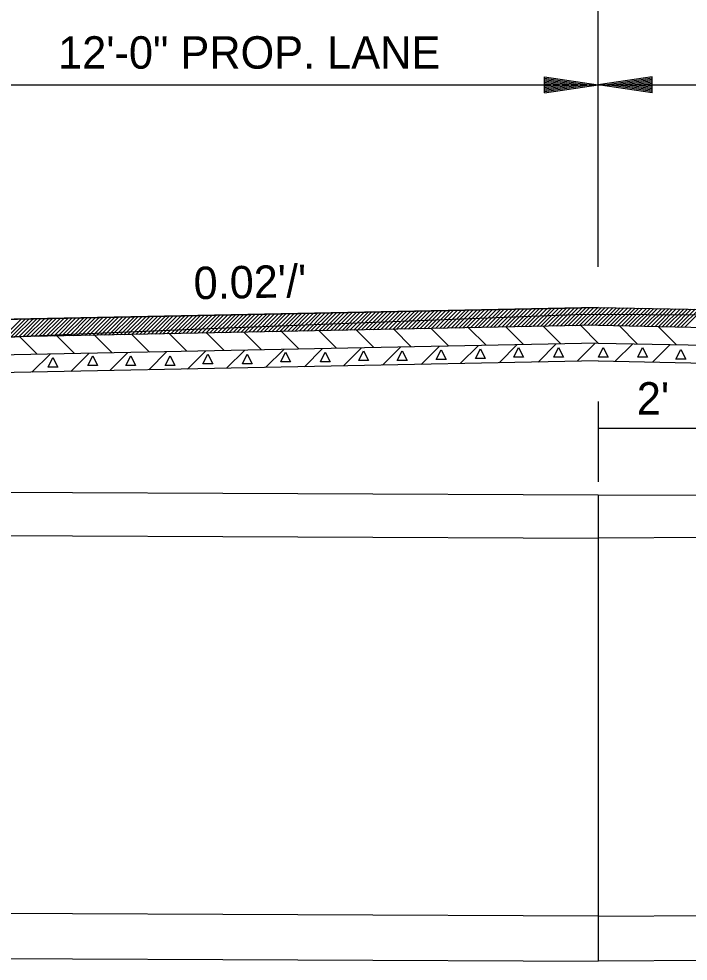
# Model space of a CAD drawing. Extents: x 1398460 to 1408037, y 380768 to 383968.
# Drawn here: x 1401391.5 to 1401515.5, y 383325.7 to 383500.2 of the extents above; entities that cross this region are included whole.
import ezdxf

# ---------------------------------------------------------------- set-up
doc = ezdxf.new("R2010")
doc.units = 0
for name, color, linetype in [('R_Dimension', 7, 'Continuous'), ('R_Draft', 7, 'Continuous'), ('R_Exist Surface', 7, 'Continuous'), ('R_Water', 7, 'Continuous')]:
    doc.layers.add(name, color=color, linetype=linetype)

msp = doc.modelspace()

# ---------------------------------------------------------------- linework, layer by layer
at = {"layer": 'R_Dimension'}
for p, q in [((1401498.88, 383454.27), (1401498.88, 383639.18)), ((1401488.88, 383489.49), (1401498.88, 383487.99)), ((1401488.88, 383486.49), (1401488.88, 383489.49)), ((1401488.88, 383489.24), (1401497.21, 383487.99)), ((1401488.88, 383488.98), (1401495.49, 383487.99)), ((1401488.88, 383488.73), (1401493.82, 383487.99)), ((1401488.88, 383488.48), (1401492.13, 383487.99)), ((1401488.88, 383488.22), (1401490.46, 383487.99)), ((1401508.88, 383489.49), (1401498.88, 383487.99)), ((1401508.88, 383489.24), (1401500.55, 383487.99)), ((1401508.88, 383488.98), (1401502.27, 383487.99)), ((1401508.88, 383488.73), (1401503.93, 383487.99)), ((1401508.88, 383488.48), (1401505.63, 383487.99)), ((1401508.88, 383488.22), (1401507.3, 383487.99)), ((1401508.88, 383486.49), (1401508.88, 383489.49)), ((1401378.88, 383487.99), (1401498.88, 383487.99)), ((1401488.88, 383486.49), (1401498.88, 383487.99)), ((1401488.88, 383487.5), (1401492.13, 383487.99)), ((1401488.88, 383486.99), (1401495.49, 383487.99)), ((1401488.88, 383486.74), (1401497.21, 383487.99)), ((1401488.88, 383487.24), (1401493.82, 383487.99)), ((1401488.88, 383487.75), (1401490.46, 383487.99)), ((1401508.88, 383486.49), (1401498.88, 383487.99)), ((1401498.88, 383487.99), (1401618.88, 383487.99)), ((1401508.88, 383486.74), (1401500.55, 383487.99)), ((1401508.88, 383486.99), (1401502.27, 383487.99)), ((1401508.88, 383487.24), (1401503.93, 383487.99)), ((1401508.88, 383487.5), (1401505.63, 383487.99)), ((1401508.88, 383487.75), (1401507.3, 383487.99)), ((1401498.88, 383429.35), (1401498.88, 383414.48)), ((1401518.88, 383424.35), (1401498.88, 383424.35))]:
    msp.add_line(p, q, dxfattribs=at)
at = {"layer": 'R_Draft'}
for p, q in [((1401498.88, 383446.78), (1401378.88, 383444.38)), ((1401467.26, 383442.84), (1401470.63, 383446.21)), ((1401467.98, 383442.86), (1401471.35, 383446.23)), ((1401468.71, 383442.87), (1401472.07, 383446.24)), ((1401469.43, 383442.89), (1401472.8, 383446.26)), ((1401470.15, 383442.9), (1401473.52, 383446.27)), ((1401470.87, 383442.92), (1401474.24, 383446.28)), ((1401471.59, 383442.93), (1401474.96, 383446.3)), ((1401472.31, 383442.95), (1401475.68, 383446.31)), ((1401473.04, 383442.96), (1401476.4, 383446.33)), ((1401473.76, 383442.97), (1401477.12, 383446.34)), ((1401474.48, 383442.99), (1401477.85, 383446.36)), ((1401475.2, 383443), (1401478.57, 383446.37)), ((1401475.92, 383443.02), (1401479.29, 383446.39)), ((1401476.64, 383443.03), (1401480.01, 383446.4)), ((1401477.36, 383443.05), (1401480.73, 383446.41)), ((1401478.09, 383443.06), (1401481.45, 383446.43)), ((1401478.81, 383443.08), (1401482.18, 383446.44)), ((1401479.53, 383443.09), (1401482.9, 383446.46)), ((1401480.25, 383443.1), (1401483.62, 383446.47)), ((1401480.97, 383443.12), (1401484.34, 383446.49)), ((1401481.69, 383443.13), (1401485.06, 383446.5)), ((1401482.42, 383443.15), (1401485.78, 383446.52)), ((1401483.14, 383443.16), (1401486.5, 383446.53)), ((1401483.86, 383443.18), (1401487.23, 383446.54)), ((1401484.58, 383443.19), (1401487.95, 383446.56)), ((1401485.3, 383443.21), (1401488.67, 383446.57)), ((1401486.02, 383443.22), (1401489.39, 383446.59)), ((1401486.74, 383443.23), (1401490.11, 383446.6)), ((1401487.47, 383443.25), (1401490.83, 383446.62)), ((1401488.19, 383443.26), (1401491.56, 383446.63)), ((1401488.91, 383443.28), (1401492.28, 383446.65)), ((1401489.63, 383443.29), (1401493, 383446.66)), ((1401490.35, 383443.31), (1401493.72, 383446.67)), ((1401491.07, 383443.32), (1401494.44, 383446.69)), ((1401491.8, 383443.33), (1401495.16, 383446.7)), ((1401492.52, 383443.35), (1401495.88, 383446.72)), ((1401493.24, 383443.36), (1401496.61, 383446.73)), ((1401493.96, 383443.38), (1401497.33, 383446.75)), ((1401494.68, 383443.39), (1401498.05, 383446.76)), ((1401495.4, 383443.41), (1401498.77, 383446.78)), ((1401496.12, 383443.42), (1401499.47, 383446.77)), ((1401496.85, 383443.44), (1401500.16, 383446.75)), ((1401497.57, 383443.45), (1401500.85, 383446.74)), ((1401498.29, 383443.46), (1401501.55, 383446.72)), ((1401498.88, 383446.78), (1401518.88, 383446.38)), ((1401499.01, 383443.47), (1401502.24, 383446.71)), ((1401499.7, 383443.46), (1401502.93, 383446.7)), ((1401500.39, 383443.45), (1401503.63, 383446.68)), ((1401501.09, 383443.43), (1401504.32, 383446.67)), ((1401501.78, 383443.42), (1401505.01, 383446.65)), ((1401502.47, 383443.4), (1401505.71, 383446.64)), ((1401503.16, 383443.39), (1401506.4, 383446.63)), ((1401503.86, 383443.38), (1401507.09, 383446.61)), ((1401504.55, 383443.36), (1401507.79, 383446.6)), ((1401505.24, 383443.35), (1401508.48, 383446.59)), ((1401505.94, 383443.34), (1401509.17, 383446.57)), ((1401506.63, 383443.32), (1401509.87, 383446.56)), ((1401507.32, 383443.31), (1401510.56, 383446.54)), ((1401508.02, 383443.29), (1401511.25, 383446.53)), ((1401508.71, 383443.28), (1401511.95, 383446.52)), ((1401509.4, 383443.27), (1401512.64, 383446.5)), ((1401510.1, 383443.25), (1401513.33, 383446.49)), ((1401510.79, 383443.24), (1401514.03, 383446.47)), ((1401511.48, 383443.22), (1401514.72, 383446.46)), ((1401512.18, 383443.21), (1401515.41, 383446.45)), ((1401512.87, 383443.2), (1401516.11, 383446.43)), ((1401513.56, 383443.18), (1401516.8, 383446.42)), ((1401514.26, 383443.17), (1401517.49, 383446.41)), ((1401514.95, 383443.16), (1401518.19, 383446.39)), ((1401388.62, 383441.27), (1401391.98, 383444.64)), ((1401389.34, 383441.29), (1401392.7, 383444.65)), ((1401390.06, 383441.3), (1401393.43, 383444.67)), ((1401390.78, 383441.31), (1401394.15, 383444.68)), ((1401391.5, 383441.33), (1401394.87, 383444.7)), ((1401392.22, 383441.34), (1401395.59, 383444.71)), ((1401392.94, 383441.36), (1401396.31, 383444.73)), ((1401393.67, 383441.37), (1401397.03, 383444.74)), ((1401394.39, 383441.39), (1401397.76, 383444.75)), ((1401395.11, 383441.4), (1401398.48, 383444.77)), ((1401395.83, 383441.42), (1401399.2, 383444.78)), ((1401396.55, 383441.43), (1401399.92, 383444.8)), ((1401397.27, 383441.44), (1401400.64, 383444.81)), ((1401398, 383441.46), (1401401.36, 383444.83)), ((1401398.72, 383441.47), (1401402.08, 383444.84)), ((1401399.44, 383441.49), (1401402.81, 383444.86)), ((1401400.16, 383441.5), (1401403.53, 383444.87)), ((1401400.88, 383441.52), (1401404.25, 383444.88)), ((1401401.6, 383441.53), (1401404.97, 383444.9)), ((1401402.32, 383441.55), (1401405.69, 383444.91)), ((1401403.05, 383441.56), (1401406.41, 383444.93)), ((1401403.77, 383441.57), (1401407.14, 383444.94)), ((1401404.49, 383441.59), (1401407.86, 383444.96)), ((1401405.21, 383441.6), (1401408.58, 383444.97)), ((1401405.93, 383441.62), (1401409.3, 383444.99)), ((1401406.65, 383441.63), (1401410.02, 383445)), ((1401407.38, 383441.65), (1401410.74, 383445.01)), ((1401408.1, 383441.66), (1401411.46, 383445.03)), ((1401408.82, 383441.68), (1401412.19, 383445.04)), ((1401409.54, 383441.69), (1401412.91, 383445.06)), ((1401410.26, 383441.7), (1401413.63, 383445.07)), ((1401410.98, 383441.72), (1401414.35, 383445.09)), ((1401411.7, 383441.73), (1401415.07, 383445.1)), ((1401412.43, 383441.75), (1401415.79, 383445.12)), ((1401413.15, 383441.76), (1401416.52, 383445.13)), ((1401413.87, 383441.78), (1401417.24, 383445.14)), ((1401414.59, 383441.79), (1401417.96, 383445.16)), ((1401415.31, 383441.81), (1401418.68, 383445.17)), ((1401416.03, 383441.82), (1401419.4, 383445.19)), ((1401416.76, 383441.83), (1401420.12, 383445.2)), ((1401417.48, 383441.85), (1401420.84, 383445.22)), ((1401418.2, 383441.86), (1401421.57, 383445.23)), ((1401418.92, 383441.88), (1401422.29, 383445.25)), ((1401419.64, 383441.89), (1401423.01, 383445.26)), ((1401420.36, 383441.91), (1401423.73, 383445.27)), ((1401421.08, 383441.92), (1401424.45, 383445.29)), ((1401421.81, 383441.94), (1401425.17, 383445.3)), ((1401422.53, 383441.95), (1401425.9, 383445.32)), ((1401423.25, 383441.96), (1401426.62, 383445.33)), ((1401423.97, 383441.98), (1401427.34, 383445.35)), ((1401424.69, 383441.99), (1401428.06, 383445.36)), ((1401425.41, 383442.01), (1401428.78, 383445.38)), ((1401426.14, 383442.02), (1401429.5, 383445.39)), ((1401426.86, 383442.04), (1401430.22, 383445.4)), ((1401427.58, 383442.05), (1401430.95, 383445.42)), ((1401428.3, 383442.07), (1401431.67, 383445.43)), ((1401429.02, 383442.08), (1401432.39, 383445.45)), ((1401429.74, 383442.09), (1401433.11, 383445.46)), ((1401430.46, 383442.11), (1401433.83, 383445.48)), ((1401431.19, 383442.12), (1401434.55, 383445.49)), ((1401431.91, 383442.14), (1401435.28, 383445.51)), ((1401432.63, 383442.15), (1401436, 383445.52)), ((1401433.35, 383442.17), (1401436.72, 383445.53)), ((1401434.07, 383442.18), (1401437.44, 383445.55)), ((1401434.79, 383442.19), (1401438.16, 383445.56)), ((1401435.52, 383442.21), (1401438.88, 383445.58)), ((1401436.24, 383442.22), (1401439.6, 383445.59)), ((1401436.96, 383442.24), (1401440.33, 383445.61)), ((1401437.68, 383442.25), (1401441.05, 383445.62)), ((1401438.4, 383442.27), (1401441.77, 383445.64)), ((1401439.12, 383442.28), (1401442.49, 383445.65)), ((1401439.84, 383442.3), (1401443.21, 383445.66)), ((1401440.57, 383442.31), (1401443.93, 383445.68)), ((1401441.29, 383442.32), (1401444.66, 383445.69)), ((1401442.01, 383442.34), (1401445.38, 383445.71)), ((1401442.73, 383442.35), (1401446.1, 383445.72)), ((1401443.45, 383442.37), (1401446.82, 383445.74)), ((1401444.17, 383442.38), (1401447.54, 383445.75)), ((1401444.9, 383442.4), (1401448.26, 383445.77)), ((1401445.62, 383442.41), (1401448.98, 383445.78)), ((1401446.34, 383442.43), (1401449.71, 383445.79)), ((1401447.06, 383442.44), (1401450.43, 383445.81)), ((1401447.78, 383442.45), (1401451.15, 383445.82)), ((1401448.5, 383442.47), (1401451.87, 383445.84)), ((1401449.22, 383442.48), (1401452.59, 383445.85)), ((1401449.95, 383442.5), (1401453.31, 383445.87)), ((1401450.67, 383442.51), (1401454.04, 383445.88)), ((1401451.39, 383442.53), (1401454.76, 383445.89)), ((1401452.11, 383442.54), (1401455.48, 383445.91)), ((1401452.83, 383442.56), (1401456.2, 383445.92)), ((1401453.55, 383442.57), (1401456.92, 383445.94)), ((1401454.28, 383442.58), (1401457.64, 383445.95)), ((1401455, 383442.6), (1401458.36, 383445.97)), ((1401455.72, 383442.61), (1401459.09, 383445.98)), ((1401456.44, 383442.63), (1401459.81, 383446)), ((1401457.16, 383442.64), (1401460.53, 383446.01)), ((1401457.88, 383442.66), (1401461.25, 383446.02)), ((1401458.6, 383442.67), (1401461.97, 383446.04)), ((1401459.33, 383442.69), (1401462.69, 383446.05)), ((1401460.05, 383442.7), (1401463.42, 383446.07)), ((1401460.77, 383442.71), (1401464.14, 383446.08)), ((1401461.49, 383442.73), (1401464.86, 383446.1)), ((1401462.21, 383442.74), (1401465.58, 383446.11)), ((1401462.93, 383442.76), (1401466.3, 383446.13)), ((1401463.66, 383442.77), (1401467.02, 383446.14)), ((1401464.38, 383442.79), (1401467.74, 383446.15)), ((1401465.1, 383442.8), (1401468.47, 383446.17)), ((1401465.82, 383442.82), (1401469.19, 383446.18)), ((1401466.54, 383442.83), (1401469.91, 383446.2)), ((1401498.88, 383443.48), (1401377.21, 383441.04)), ((1401460.98, 383442.72), (1401464.22, 383439.48)), ((1401467.91, 383442.86), (1401471.15, 383439.62)), ((1401474.85, 383443), (1401478.08, 383439.76)), ((1401481.78, 383443.13), (1401485.01, 383439.9)), ((1401488.71, 383443.27), (1401491.95, 383440.04)), ((1401495.64, 383443.41), (1401498.88, 383440.18)), ((1401498.88, 383443.48), (1401518.88, 383443.08)), ((1401502.73, 383443.4), (1401506.09, 383440.03)), ((1401509.94, 383443.26), (1401513.31, 383439.89)), ((1401391.66, 383441.33), (1401394.89, 383438.1)), ((1401398.59, 383441.47), (1401401.83, 383438.24)), ((1401405.52, 383441.61), (1401408.76, 383438.37)), ((1401412.45, 383441.75), (1401415.69, 383438.51)), ((1401419.39, 383441.89), (1401422.62, 383438.65)), ((1401426.32, 383442.03), (1401429.55, 383438.79)), ((1401433.25, 383442.16), (1401436.49, 383438.93)), ((1401440.18, 383442.3), (1401443.42, 383439.07)), ((1401447.12, 383442.44), (1401450.35, 383439.21)), ((1401454.05, 383442.58), (1401457.28, 383439.34)), ((1401498.88, 383440.18), (1401375.55, 383437.71)), ((1401451.64, 383435.93), (1401455.01, 383439.3)), ((1401458.86, 383436.08), (1401462.22, 383439.44)), ((1401466.07, 383436.22), (1401469.44, 383439.59)), ((1401473.29, 383436.36), (1401476.65, 383439.73)), ((1401480.5, 383436.51), (1401483.87, 383439.88)), ((1401487.72, 383436.65), (1401491.08, 383440.02)), ((1401494.93, 383436.8), (1401498.3, 383440.17)), ((1401498.88, 383440.18), (1401518.88, 383439.78)), ((1401502.02, 383436.81), (1401505.26, 383440.05)), ((1401508.95, 383436.68), (1401512.19, 383439.91)), ((1401393.92, 383434.78), (1401397.28, 383438.14)), ((1401401.13, 383434.92), (1401404.5, 383438.29)), ((1401408.35, 383435.07), (1401411.72, 383438.43)), ((1401415.56, 383435.21), (1401418.93, 383438.58)), ((1401422.78, 383435.35), (1401426.15, 383438.72)), ((1401429.99, 383435.5), (1401433.36, 383438.87)), ((1401437.21, 383435.64), (1401440.58, 383439.01)), ((1401444.43, 383435.79), (1401447.79, 383439.15)), ((1401498.88, 383436.88), (1401373.88, 383434.38)), ((1401498.88, 383436.88), (1401518.88, 383436.48))]:
    msp.add_line(p, q, dxfattribs=at)
msp.add_lwpolyline([(1401318.88, 383441.98), (1401378.88, 383444.38), (1401498.88, 383446.78)], dxfattribs=at)
for points in [[(1401485.01, 383437.57), (1401483.21, 383437.57), (1401484.11, 383439.37)], [(1401492.42, 383437.57), (1401490.62, 383437.57), (1401491.52, 383439.37)], [(1401500.7, 383437.57), (1401498.9, 383437.57), (1401499.8, 383439.37)], [(1401507.99, 383437.57), (1401506.19, 383437.57), (1401507.09, 383439.37)], [(1401398.7, 383435.68), (1401396.9, 383435.68), (1401397.8, 383437.48)], [(1401406.09, 383436.02), (1401404.29, 383436.02), (1401405.19, 383437.82)], [(1401413.12, 383436.02), (1401411.32, 383436.02), (1401412.22, 383437.82)], [(1401420.42, 383436.02), (1401418.62, 383436.02), (1401419.52, 383437.82)], [(1401427.42, 383436.33), (1401425.62, 383436.33), (1401426.52, 383438.13)], [(1401434.72, 383436.33), (1401432.92, 383436.33), (1401433.82, 383438.13)], [(1401441.84, 383436.69), (1401440.04, 383436.69), (1401440.94, 383438.49)], [(1401449.17, 383436.69), (1401447.37, 383436.69), (1401448.27, 383438.49)], [(1401456.27, 383436.92), (1401454.47, 383436.92), (1401455.37, 383438.72)], [(1401463.43, 383436.92), (1401461.63, 383436.92), (1401462.53, 383438.72)], [(1401470.66, 383437.13), (1401468.86, 383437.13), (1401469.76, 383438.93)], [(1401477.92, 383437.32), (1401476.12, 383437.32), (1401477.02, 383439.12)], [(1401515.07, 383437.21), (1401513.27, 383437.21), (1401514.17, 383439.01)]]:
    msp.add_lwpolyline(points, close=True, dxfattribs=at)
at = {"layer": 'R_Exist Surface'}
msp.add_lwpolyline([(1400860.62, 383376.7), (1400907, 383354.28), (1400940.86, 383332.12), (1401045.76, 383333.11), (1401151.13, 383326.36), (1401196.75, 383331.07), (1401202.25, 383331.58), (1401276.34, 383380.48), (1401326.87, 383423.96), (1401338.8, 383437.28), (1401356.21, 383438.58), (1401392.29, 383441.42), (1401426.8, 383442.84), (1401496.14, 383445.51), (1401531.37, 383445.32), (1401595.85, 383444.59), (1401631.24, 383442.98), (1401649.93, 383442.13), (1401667.5, 383439.36), (1401669.33, 383438.98), (1401672.56, 383434.42), (1401687.05, 383422.29), (1401773.43, 383346.69)], dxfattribs=at)
at = {"layer": 'R_Water'}
for p, q in [((1401498.88, 383411.98), (1401164.2, 383413.56)), ((1401498.88, 383411.98), (1401833.56, 383413.56)), ((1401498.88, 383411.98), (1401498.88, 383325.71)), ((1401154.2, 383405.64), (1401498.88, 383404.05)), ((1401843.56, 383405.64), (1401498.88, 383404.05)), ((1401498.88, 383334.05), (1401063.08, 383336.06)), ((1401498.88, 383334.05), (1401934.68, 383336.06)), ((1401063.08, 383327.72), (1401498.88, 383325.71)), ((1401934.68, 383327.72), (1401498.88, 383325.71))]:
    msp.add_line(p, q, dxfattribs=at)

# ---------------------------------------------------------------- texts
at = {"layer": 'R_Dimension'}
for s, p in [('12\'-0" PROP. LANE', (1401398.77, 383490.99)), ("2'", (1401506.01, 383426.93))]:
    msp.add_text(s, height=6, dxfattribs=at).set_placement(p)
at = {"layer": 'R_Draft'}
msp.add_text("0.02'/'", height=6, rotation=1.1458, dxfattribs=at).set_placement((1401423.94, 383448.28))

doc.saveas('drawing.dxf')
